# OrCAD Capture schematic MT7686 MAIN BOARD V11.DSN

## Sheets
1 22_Straping Option: size C; title: 22_Straping Option
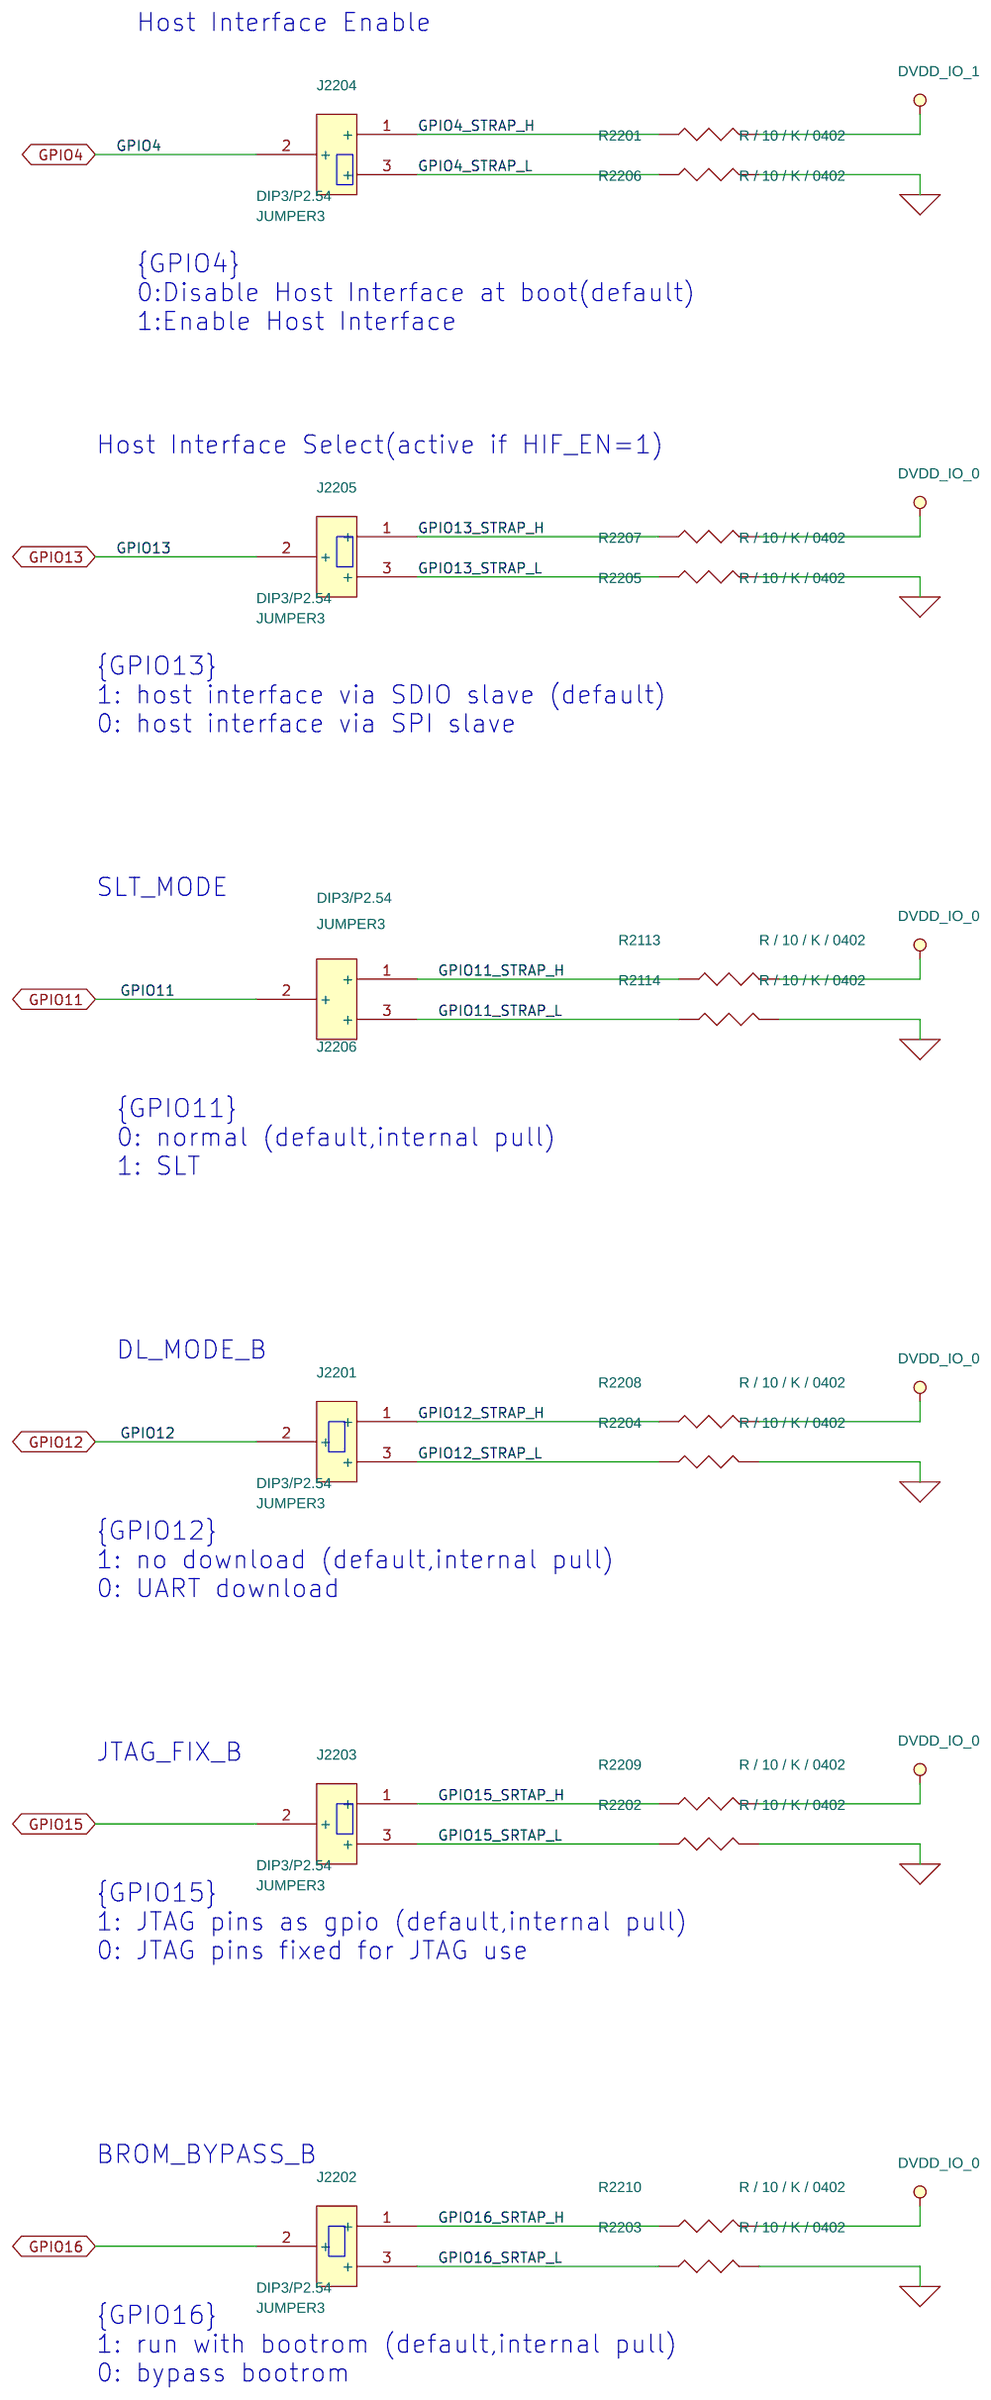
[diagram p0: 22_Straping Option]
2 90_Debug: size C; title: 90_Debug Interface
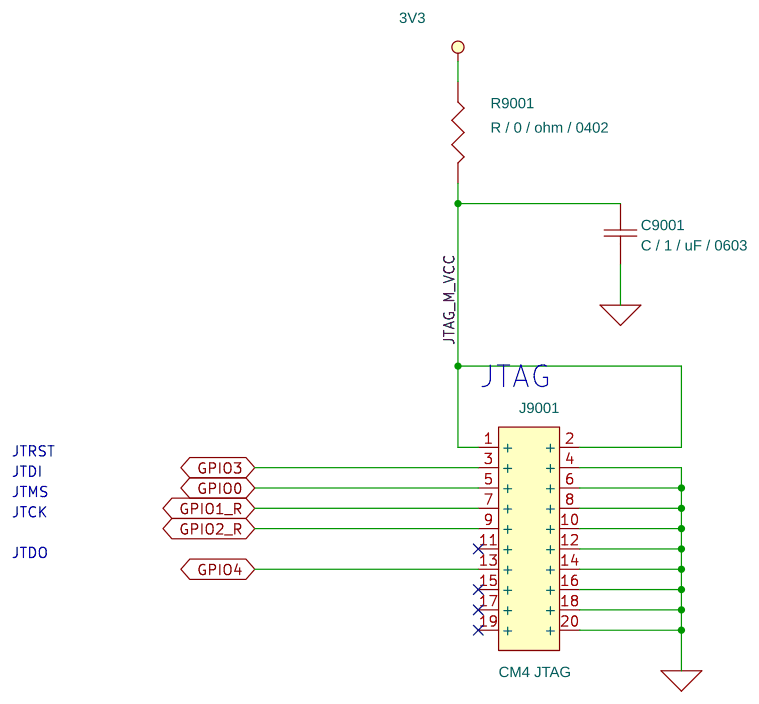
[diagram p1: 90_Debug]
3 40_external Flash: size C; title: 40_MEMORY_ Serial Flash
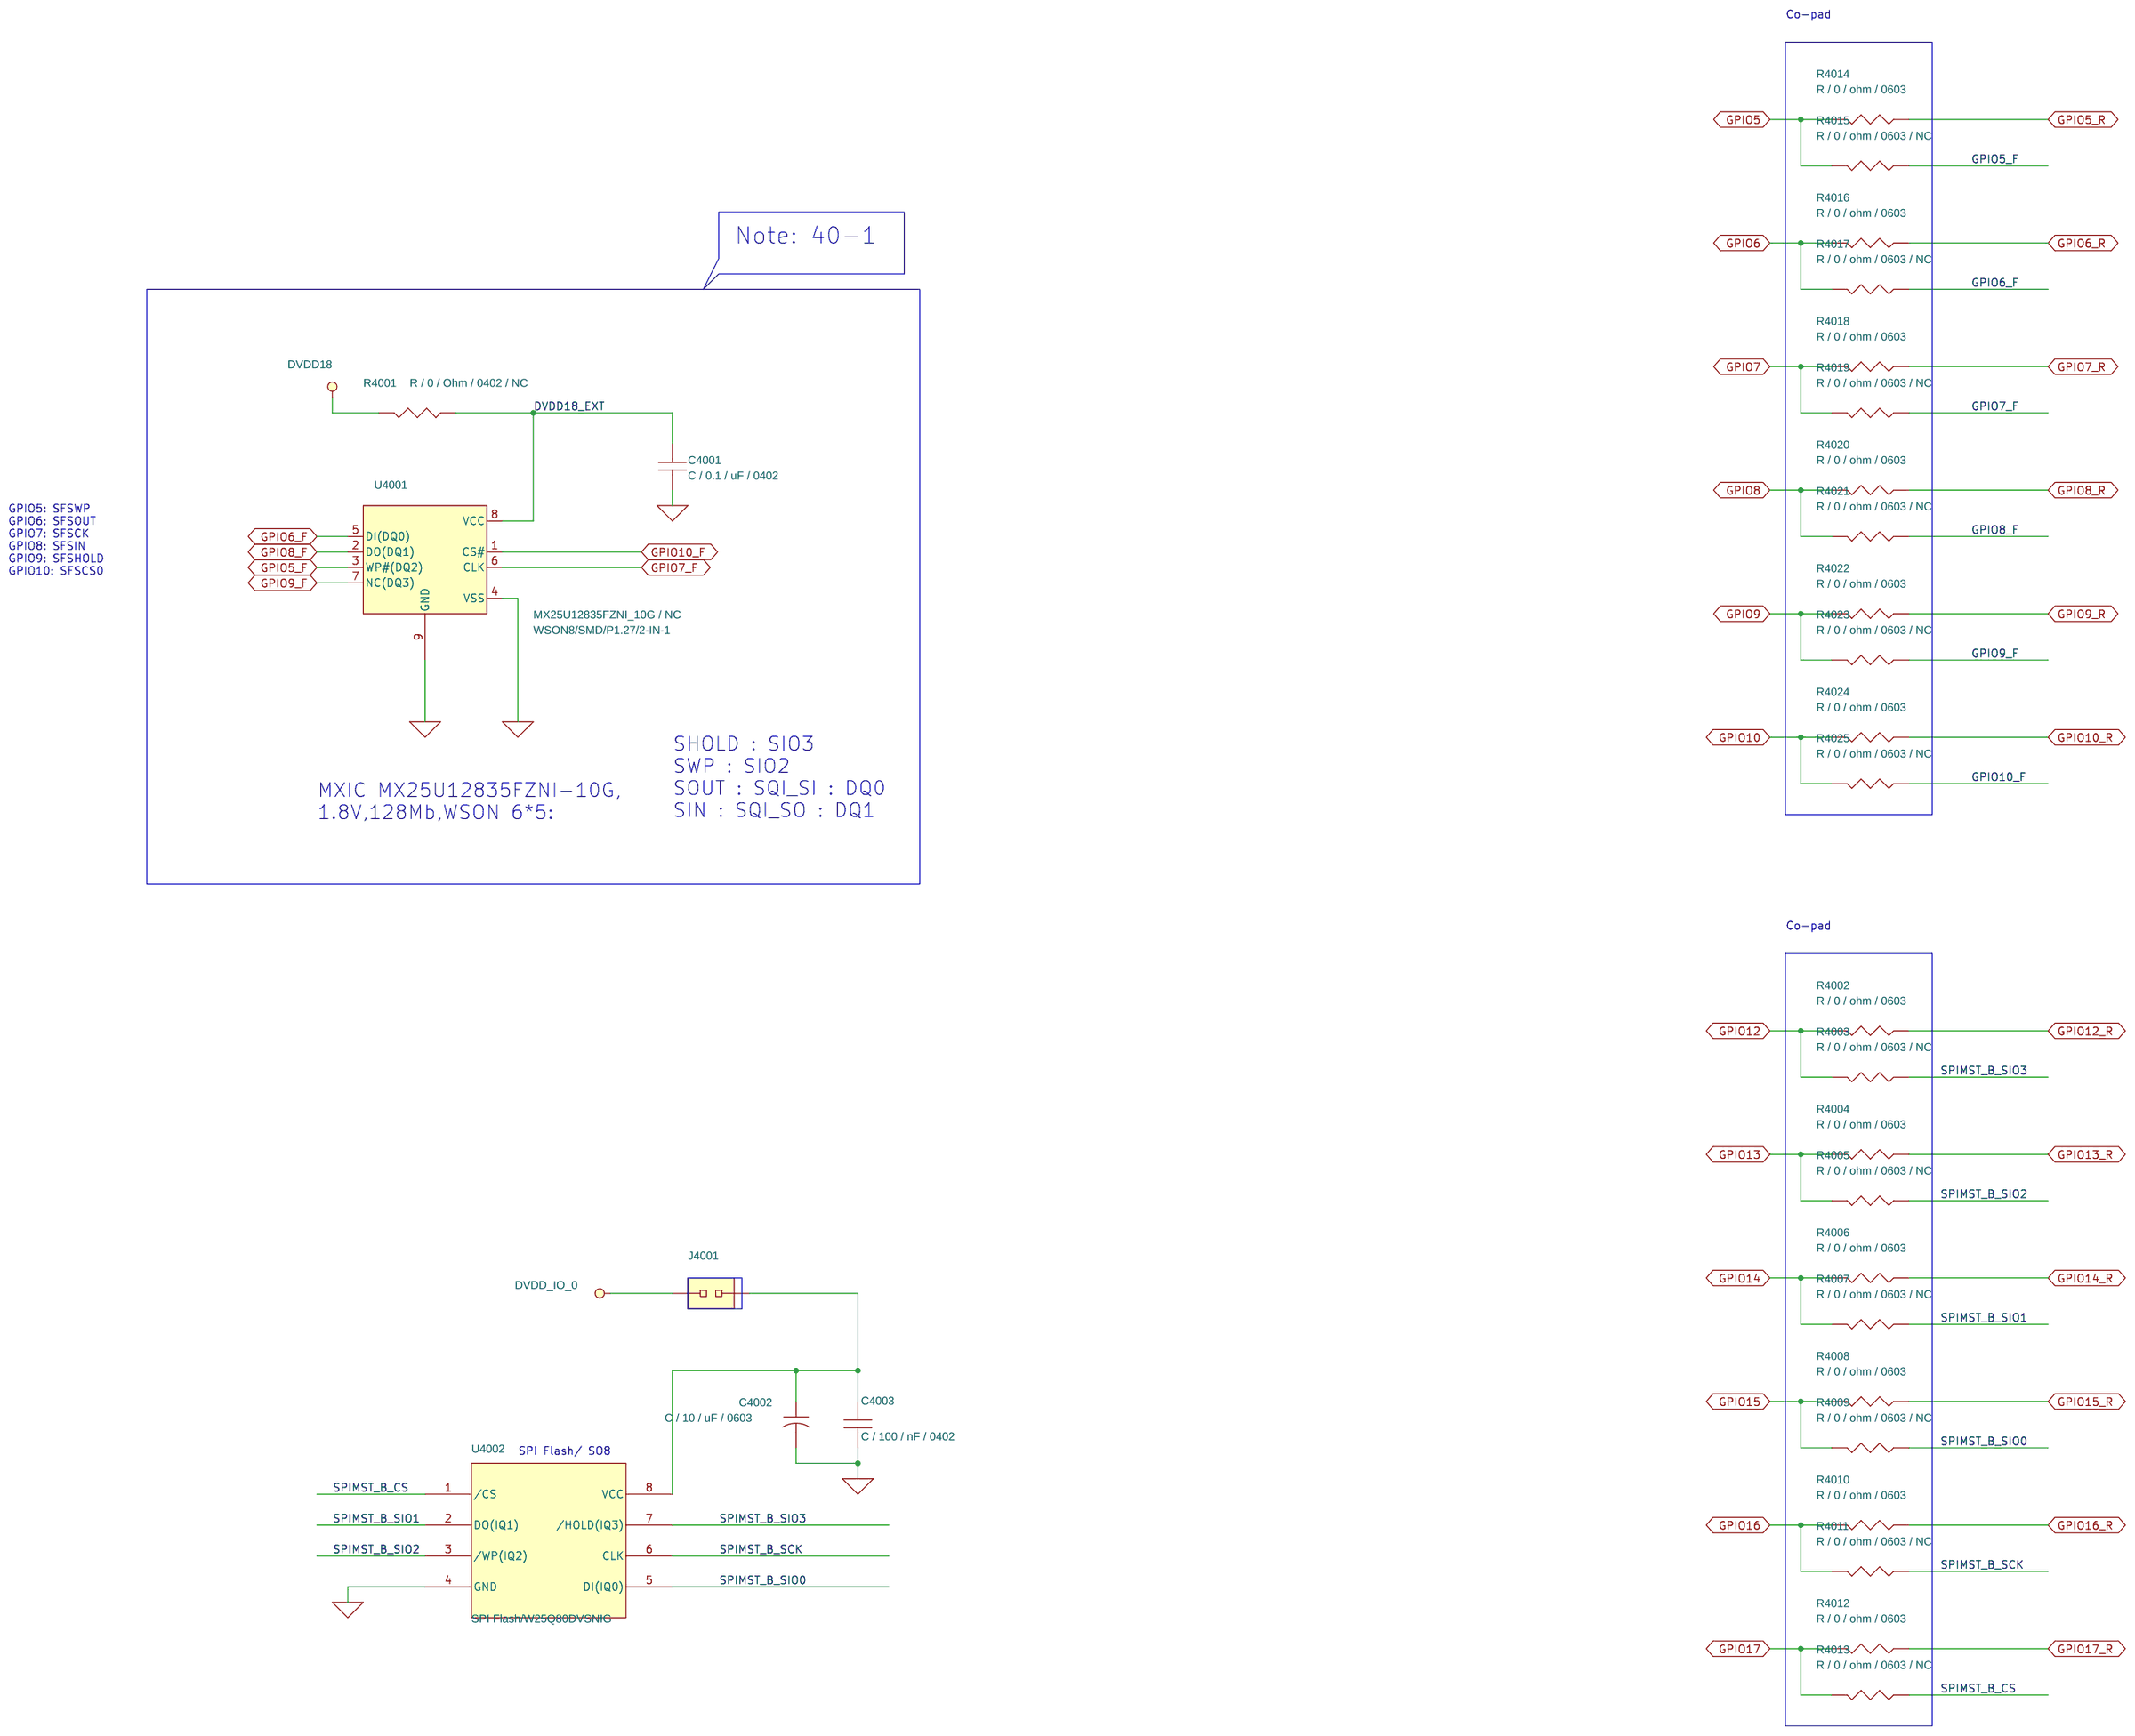
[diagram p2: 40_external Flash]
4 41_LED: size C; title: MT76x7 Main Board; rev: 3.0; company: MediaTek Inc.; note: 4_LED
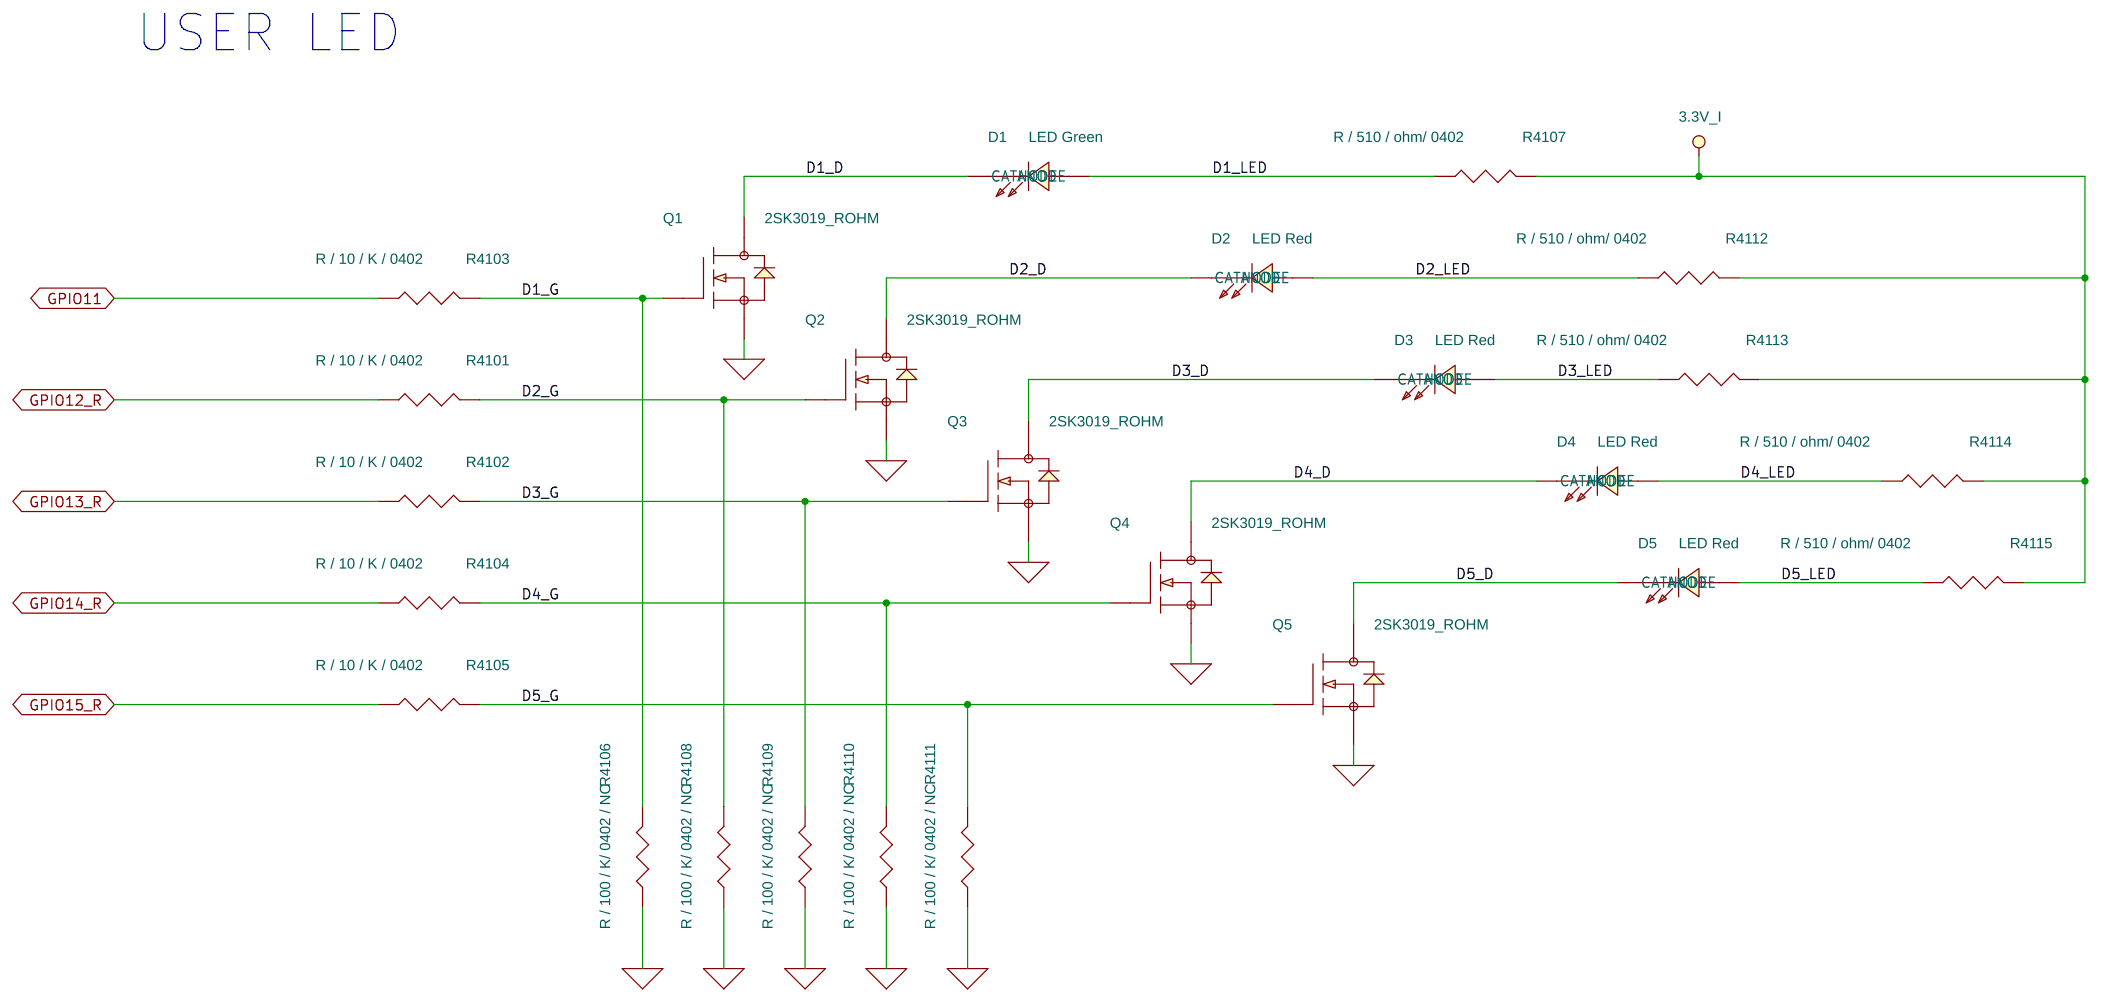
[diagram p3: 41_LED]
5 30_USB: size C; title: MT76x7 Main Board; rev: 3.0; company: MediaTek Inc.; note: 3_USB
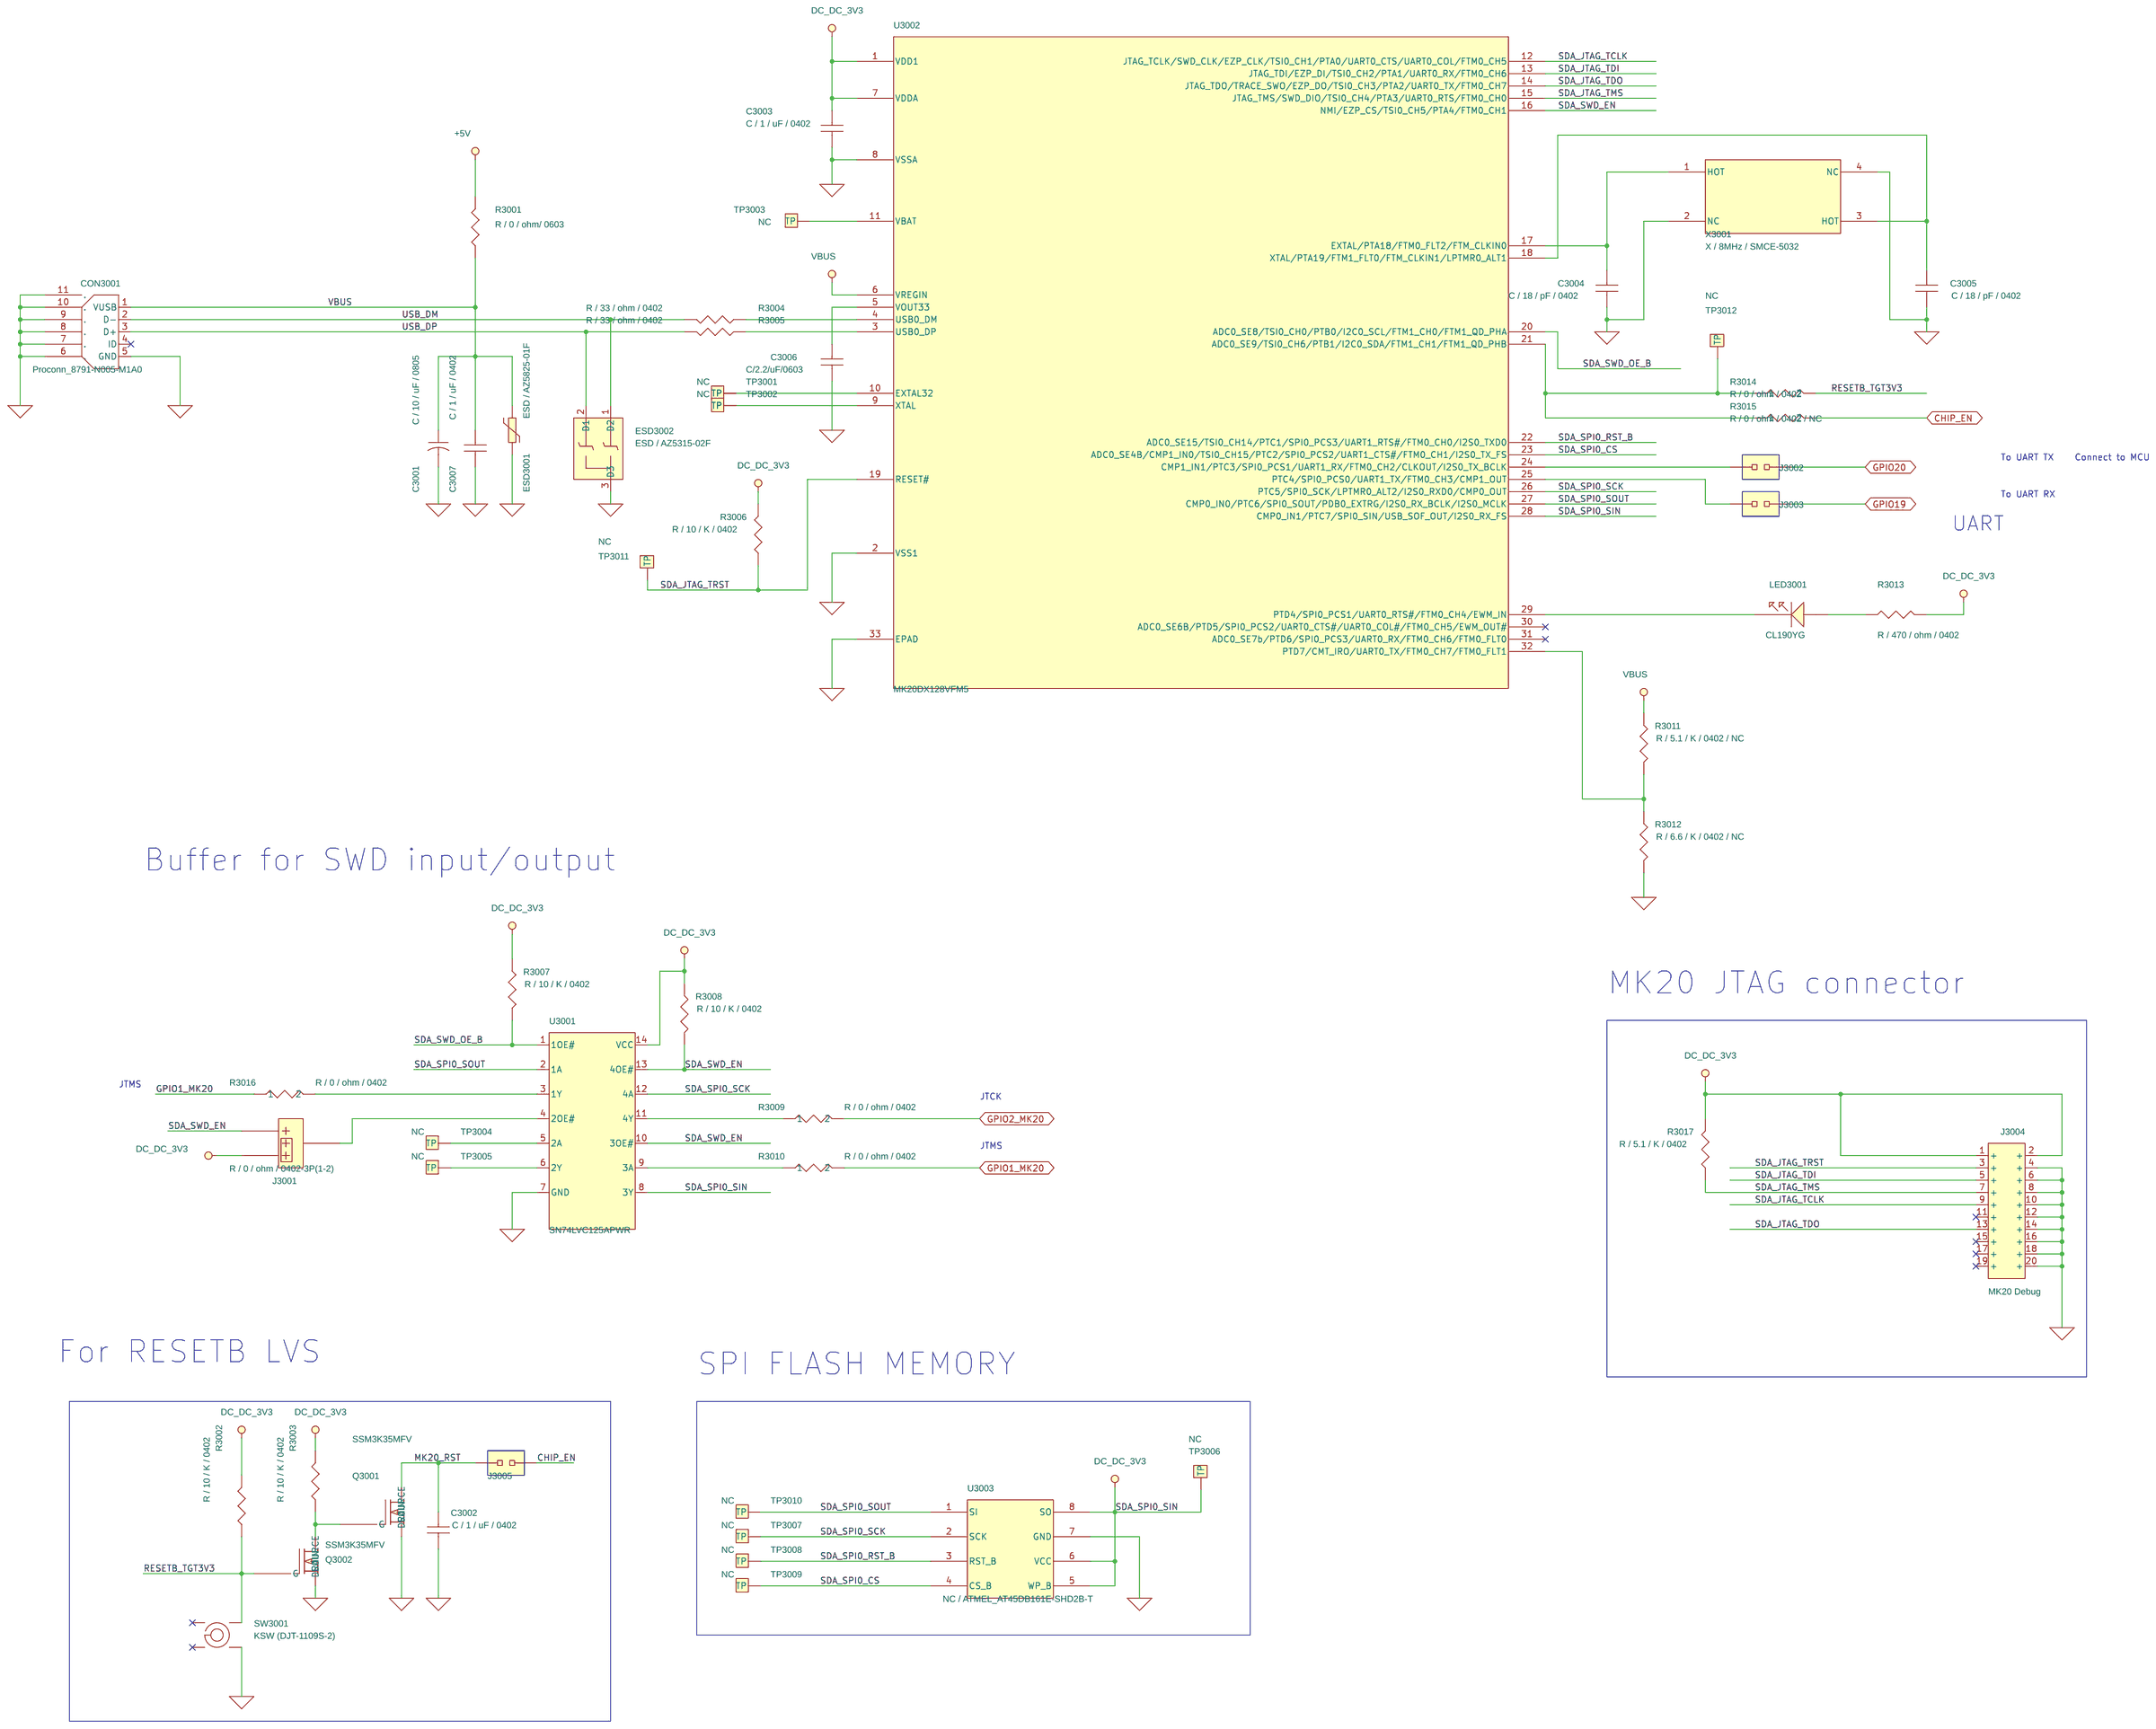
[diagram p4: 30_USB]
6 20_Power Tree: size C; title: 20_Power Tree
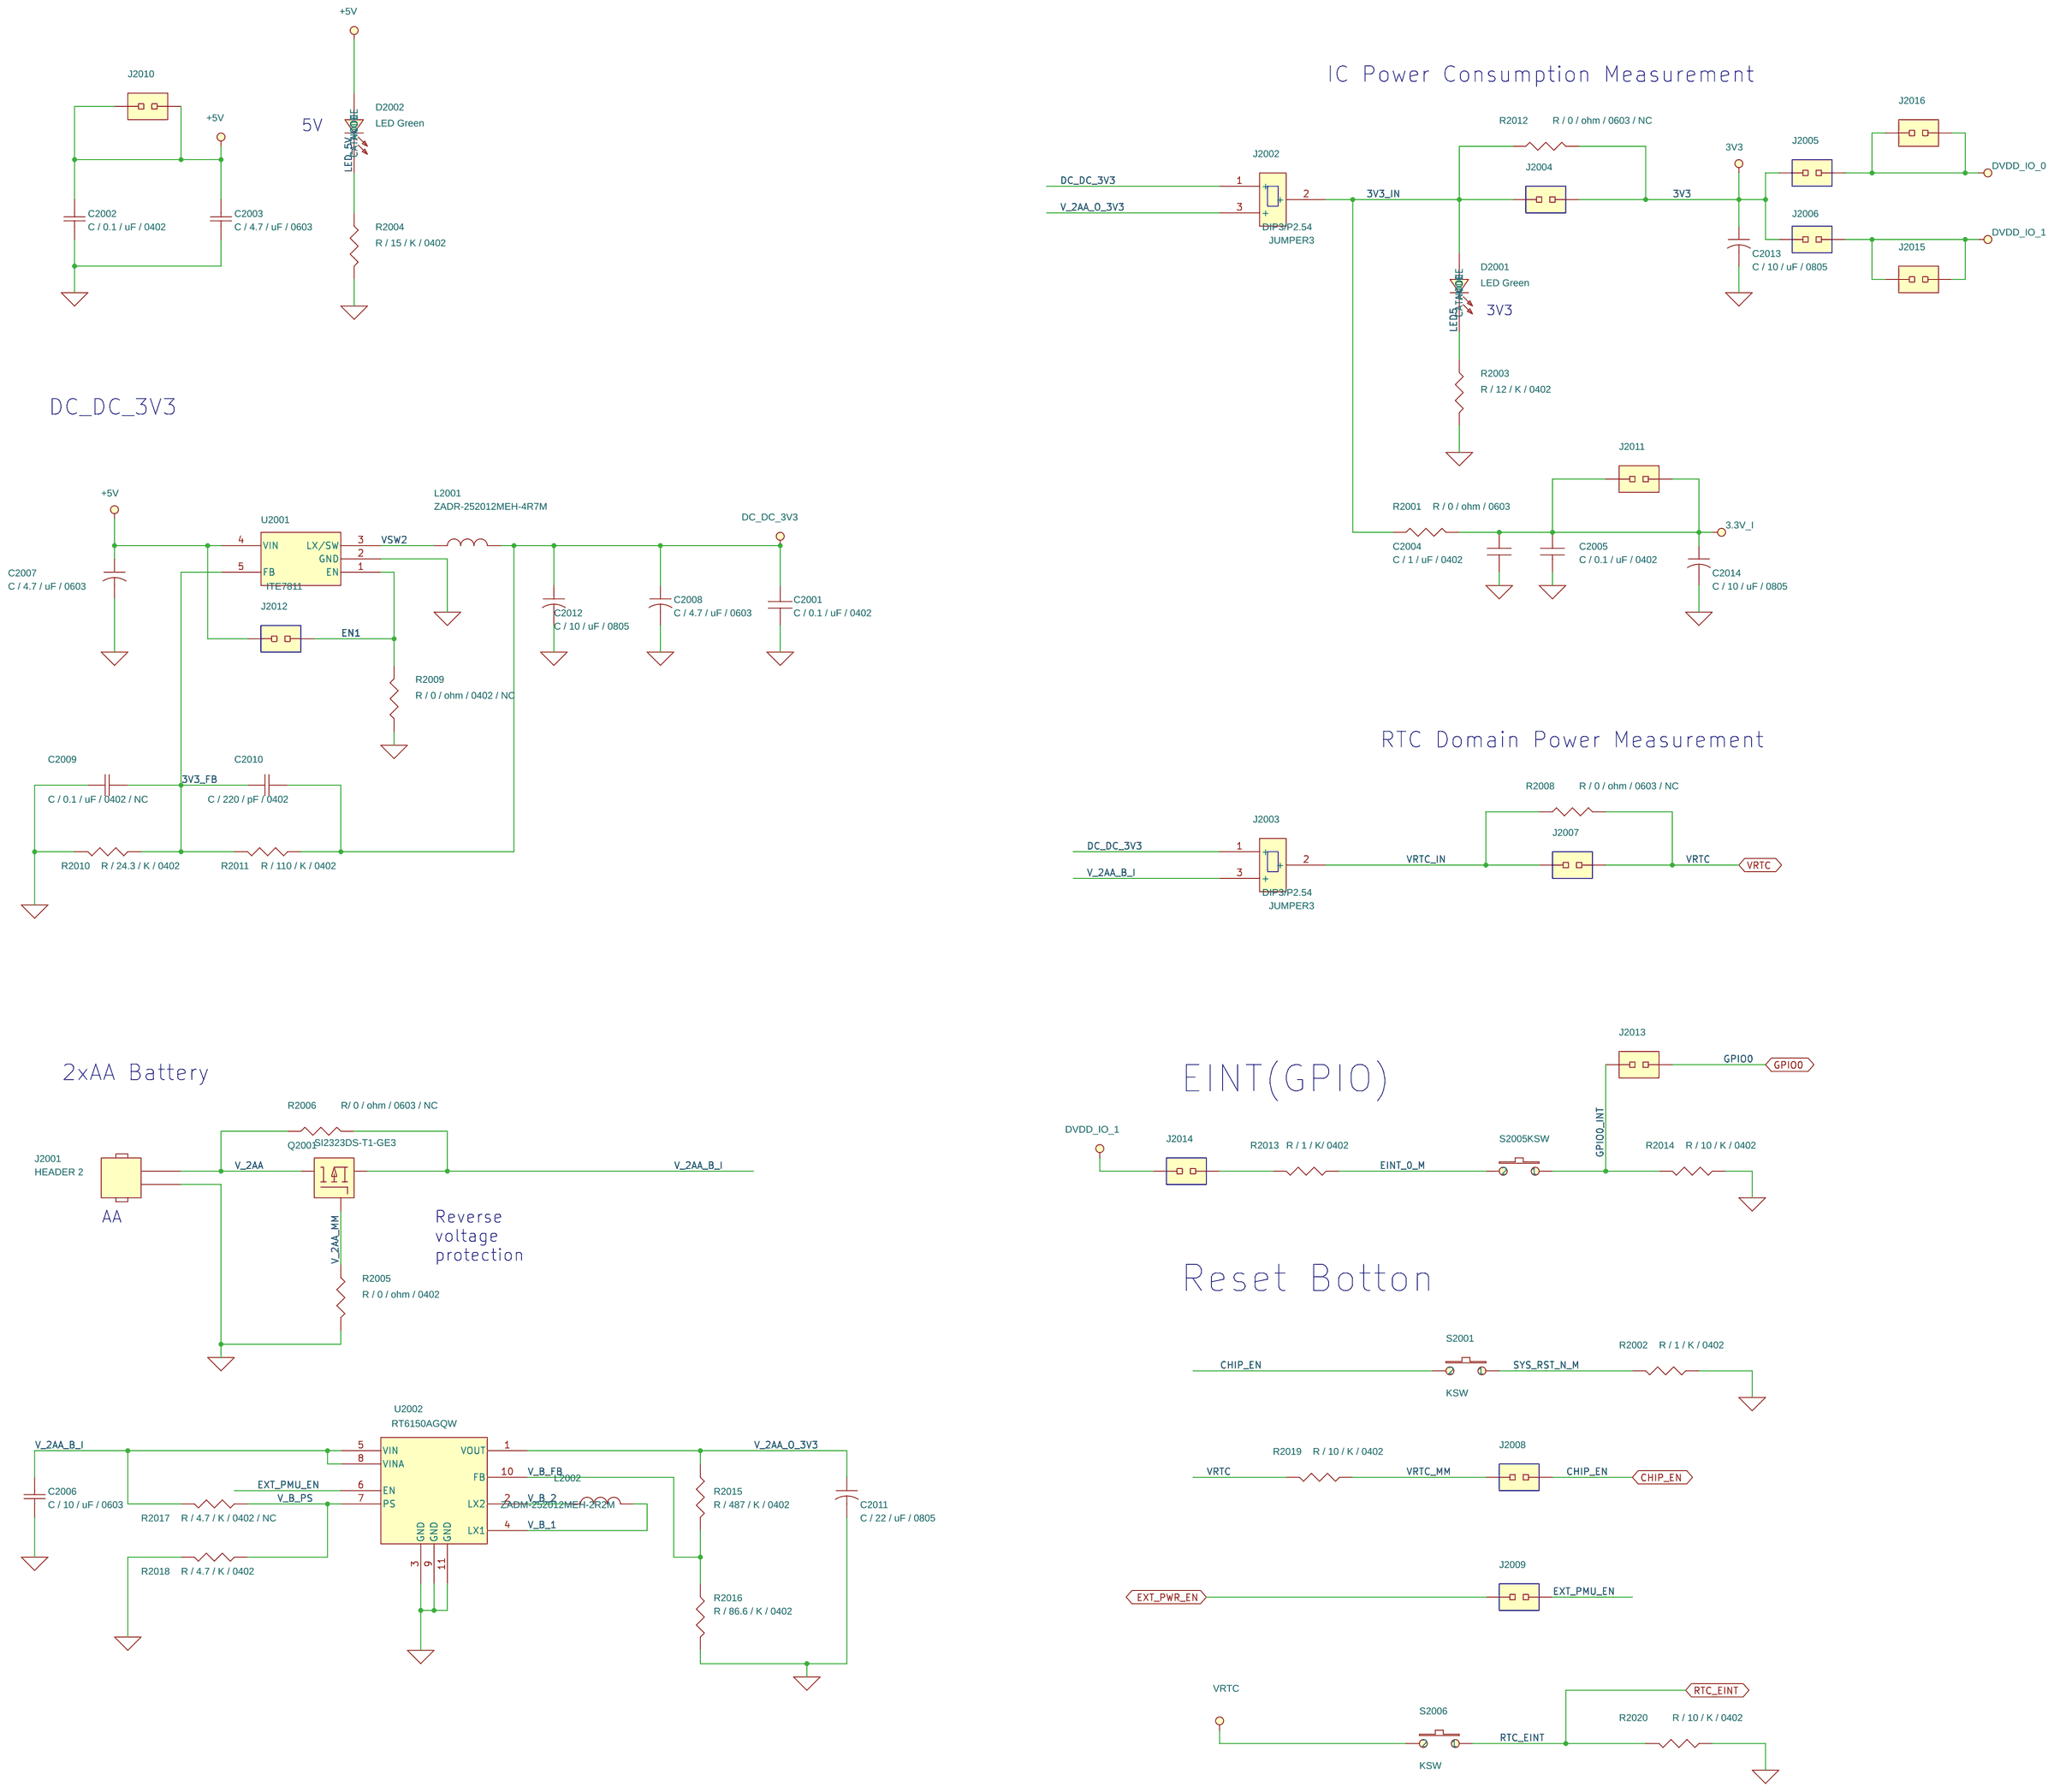
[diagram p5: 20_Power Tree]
7 21_Test Interface: size C; title: MT76x7 Main Board; rev: 3.0; company: MediaTek Inc.; note: 2_Test Interface
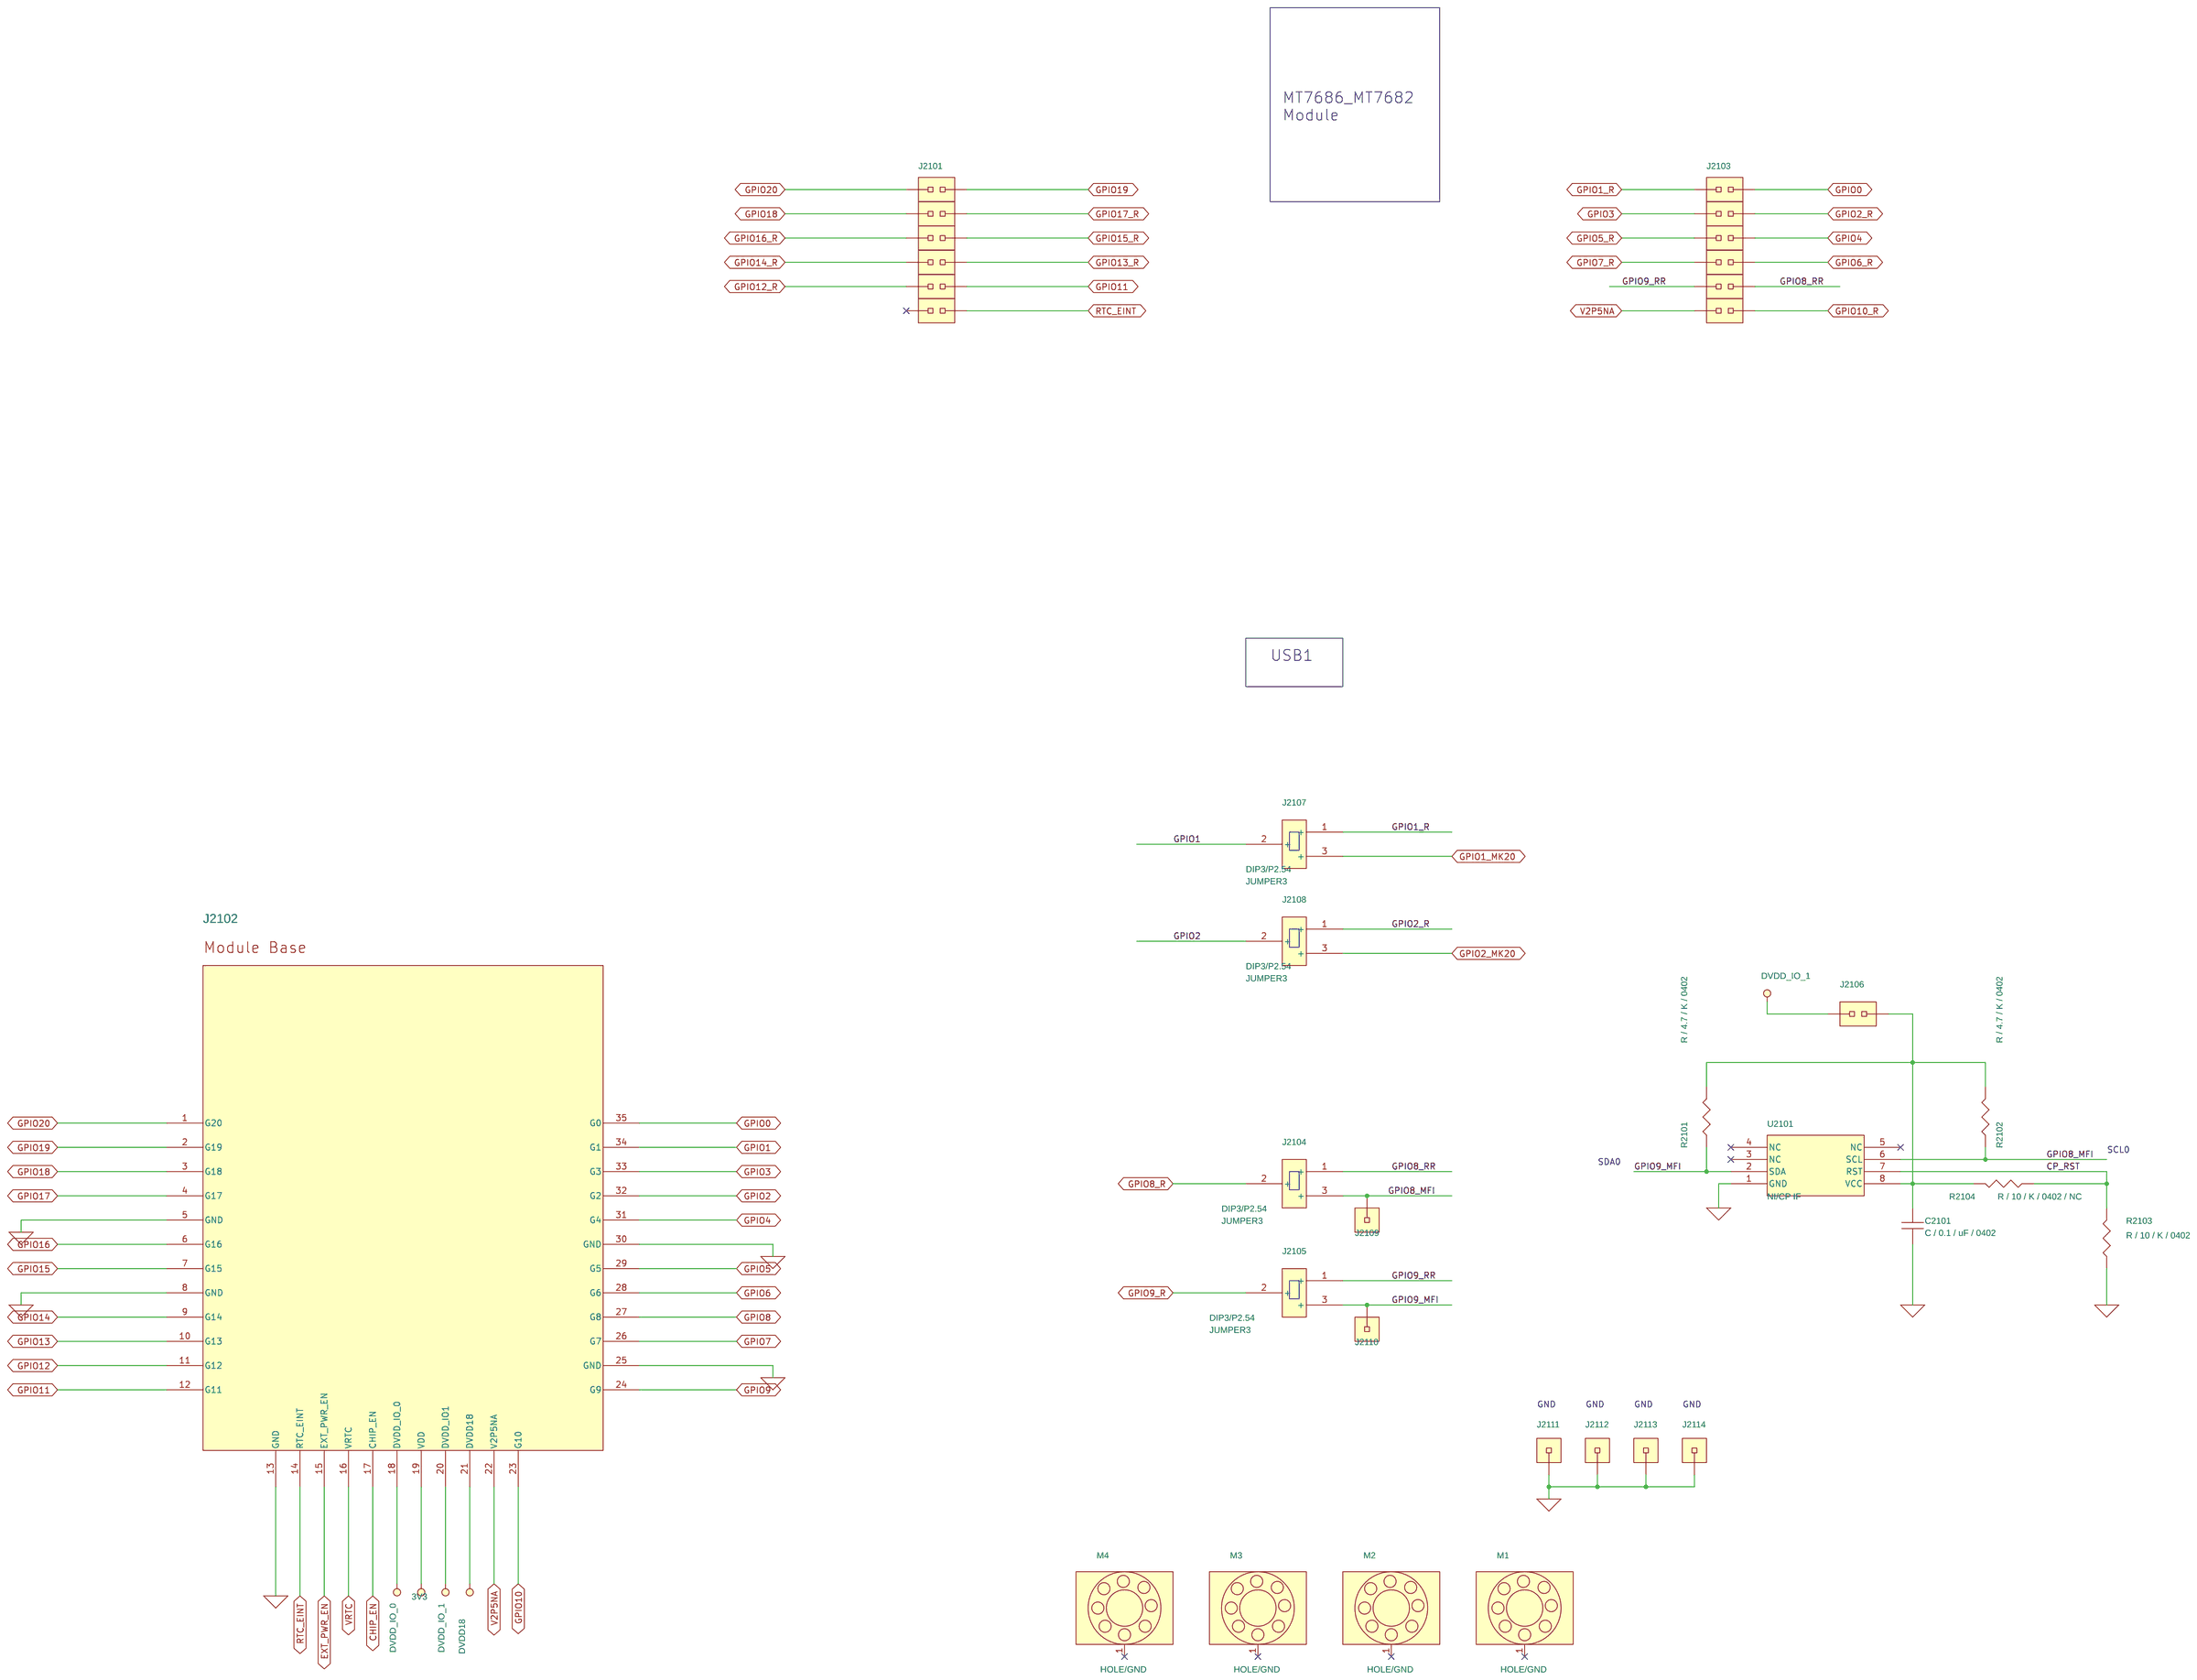
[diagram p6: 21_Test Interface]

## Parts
sheet 20_Power Tree
C2001  C / 0.1 / uF / 0402  [C0402]
C2002  C / 0.1 / uF / 0402  [C0402]
C2003  C / 4.7 / uF / 0603  [C0603]
C2004  C / 1 / uF / 0402  [C0402]
C2005  C / 0.1 / uF / 0402  [C0402]
C2006  C / 10 / uF / 0603  [C0603]
C2007  C / 4.7 / uF / 0603  [C0603]
C2008  C / 4.7 / uF / 0603  [C0603]
C2009  C / 0.1 / uF / 0402 / NC  [C0402]
C2010  C / 220 / pF / 0402  [C0402]
C2011  C / 22 / uF / 0805  [C0805]
C2012  C / 10 / uF / 0805  [C0805]
C2013  C / 10 / uF / 0805  [C0805]
C2014  C / 10 / uF / 0805  [C0805]
D2001  LED Green  [LED/SMD/0603]
D2002  LED Green  [LED/SMD/0603]
J2001  HEADER 2  [DIP2/P2.54]
J2002  JUMPER3  [DIP3/P2.54]
J2003  JUMPER3  [DIP3/P2.54]
J2004  HE2  [DIP2/P2.54]
J2005  HE2  [DIP2/P2.54]
J2006  HE2  [DIP2/P2.54]
J2007  HE2  [DIP2/P2.54]
J2008  HE2  [DIP2/P2.54]
J2009  HE2  [DIP2/P2.54]
J2010  HE2  [DIP2/P2.54]
J2011  HE2  [DIP2/P2.54]
J2012  HE2  [DIP2/P2.54]
J2013  HE2  [DIP2/P2.54]
J2014  HE2  [DIP2/P2.54]
J2015  HE2  [DIP2/P2.54]
J2016  HE2  [DIP2/P2.54]
L2001  ZADR-252012MEH-4R7M  [L/IND/SMD/VLS252010T]
L2002  ZADM-252012MEH-2R2M  [L/IND/SMD/VLS252012E]
Q2001  SI2323DS-T1-GE3  [SOT23/3P/SMD/SI2323DS]
R2001  R / 0 / ohm / 0603  [R0603]
R2002  R / 1 / K / 0402  [R0402]
R2003  R / 12 / K / 0402  [R0402]
R2004  R / 15 / K / 0402  [R0402]
R2005  R / 0 / ohm / 0402  [R0402]
R2006  R/ 0 / ohm / 0603 / NC  [R0603]
R2008  R / 0 / ohm / 0603 / NC  [R0603]
R2009  R / 0 / ohm / 0402 / NC  [R0402]
R2010  R / 24.3 / K / 0402  [R0402]
R2011  R / 110 / K / 0402  [R0402]
R2012  R / 0 / ohm / 0603 / NC  [R0603]
R2013  R / 1 / K/ 0402  [R0402]
R2014  R / 10 / K / 0402  [R0402]
R2015  R / 487 / K / 0402  [R0402]
R2016  R / 86.6 / K / 0402  [R0402]
R2017  R / 4.7 / K / 0402 / NC  [R0402]
R2018  R / 4.7 / K / 0402  [R0402]
R2019  R / 10 / K / 0402  [R0402]
R2020  R / 10 / K / 0402  [R0402]
S2001  KSW  [SW4P/DIP/WCP]
S2005  KSW  [SW4P/DIP/WCP]
S2006  KSW  [SW4P/DIP/WCP]
U2001  ITE7811  [TSOT-25/SMD/IT7811TS]
U2002  RT6150AGQW  [WDFN10/SMD/P0.5/RT6150]
sheet 21_Test Interface
C2101  C / 0.1 / uF / 0402  [C0402]
J2101  JUMPER 6x2 DIP/P2.54  [DIP6X2/P2.54]
J2102  pin to pin module  [MODULE/35P/SMD/SB-MT7686-MT7682]
J2103  JUMPER 6x2 DIP/P2.54  [DIP6X2/P2.54]
J2104  JUMPER3  [DIP3/P2.54]
J2105  JUMPER3  [DIP3/P2.54]
J2106  HE2  [DIP2/P2.54]
J2107  JUMPER3  [DIP3/P2.54]
J2108  JUMPER3  [DIP3/P2.54]
J2109  JUMPER 1x1 DIP/P2.54  [DIP1/P2.54]
J2110  JUMPER 1x1 DIP/P2.54  [DIP1/P2.54]
J2111  JUMPER 1x1 DIP/P2.54  [DIP1/P2.54]
J2112  JUMPER 1x1 DIP/P2.54  [DIP1/P2.54]
J2113  JUMPER 1x1 DIP/P2.54  [DIP1/P2.54]
J2114  JUMPER 1x1 DIP/P2.54  [DIP1/P2.54]
M1  HOLE/GND  [HOLE/NPTH/D3]
M2  HOLE/GND  [HOLE/NPTH/D3]
M3  HOLE/GND  [HOLE/NPTH/D3]
M4  HOLE/GND  [HOLE/NPTH/D3]
R2101  R / 4.7 / K / 0402  [R0402/FCS]
R2102  R / 4.7 / K / 0402  [R0402/FCS]
R2103  R / 10 / K / 0402  [R0402]
R2104  R / 10 / K / 0402 / NC  [R0402]
U2101  NI/CP IF  [USON8/SMD/P0.5/CP]
sheet 22_Straping Option
J2201  JUMPER3  [DIP3/P2.54]
J2202  JUMPER3  [DIP3/P2.54]
J2203  JUMPER3  [DIP3/P2.54]
J2204  JUMPER3  [DIP3/P2.54]
J2205  JUMPER3  [DIP3/P2.54]
J2206  JUMPER3  [DIP3/P2.54]
R2113  R / 10 / K / 0402  [R0402]
R2114  R / 10 / K / 0402  [R0402]
R2201  R / 10 / K / 0402  [R0402]
R2202  R / 10 / K / 0402  [R0402]
R2203  R / 10 / K / 0402  [R0402]
R2204  R / 10 / K / 0402  [R0402]
R2205  R / 10 / K / 0402  [R0402]
R2206  R / 10 / K / 0402  [R0402]
R2207  R / 10 / K / 0402  [R0402]
R2208  R / 10 / K / 0402  [R0402]
R2209  R / 10 / K / 0402  [R0402]
R2210  R / 10 / K / 0402  [R0402]
sheet 30_USB
C3001  C / 10 / uF / 0805  [C0805]
C3002  C / 1 / uF / 0402  [C0402]
C3003  C / 1 / uF / 0402  [C0402]
C3004  C / 18 / pF / 0402  [C0402]
C3005  C / 18 / pF / 0402  [C0402]
C3006  C/2.2/uF/0603  [C0603]
C3007  C / 1 / uF / 0402  [C0402]
CON3001  Proconn_8791-N005-M1A0  [MICROUSB/5P/SMD/P0.65/R/8791-N005-M1A0]
ESD3001  ESD / AZ5825-01F  [VR0402]
ESD3002  ESD / AZ5315-02F  [ESD/SMD/AZ5315-02F]
J3001  R / 0 / ohm / 0402-3P(1-2)  [R0402/(1-2)]
J3002  HE2  [DIP2/P2.54]
J3003  HE2  [DIP2/P2.54]
J3004  MK20 Debug  [DIP10X2/W/H/IDE/P2.54]
J3005  HE2  [DIP2/P2.54]
LED3001  CL190YG  [LED190]
Q3001  SSM3K35MFV  [2-1L1B/SMD/SSM3K35MFV]
Q3002  SSM3K35MFV  [2-1L1B/SMD/SSM3K35MFV]
R3001  R / 0 / ohm/ 0603  [R0603]
R3002  R / 10 / K / 0402  [R0402]
R3003  R / 10 / K / 0402  [R0402]
R3004  R / 33 / ohm / 0402  [R0402]
R3005  R / 33 / ohm / 0402  [R0402]
R3006  R / 10 / K / 0402  [R0402]
R3007  R / 10 / K / 0402  [R0402]
R3008  R / 10 / K / 0402  [R0402]
R3009  R / 0 / ohm / 0402  [R0402]
R3010  R / 0 / ohm / 0402  [R0402]
R3011  R / 5.1 / K / 0402 / NC  [R0402]
R3012  R / 6.6 / K / 0402 / NC  [R0402]
R3013  R / 470 / ohm / 0402  [R0402]
R3014  R / 0 / ohm / 0402  [R0402]
R3015  R / 0 / ohm / 0402 / NC  [R0402]
R3016  R / 0 / ohm / 0402  [R0402]
R3017  R / 5.1 / K / 0402  [R0402]
SW3001  KSW (DJT-1109S-2)  [SW/4P/SMD/SHOWMAN]
TP3001  NC  [TP30MIL]
TP3002  NC  [TP30MIL]
TP3003  NC  [TP30MIL]
TP3004  NC  [TP40MIL]
TP3005  NC  [TP40MIL]
TP3006  NC  [TP30MIL]
TP3007  NC  [TP30MIL]
TP3008  NC  [TP30MIL]
TP3009  NC  [TP30MIL]
TP3010  NC  [TP30MIL]
TP3011  NC  [TP30MIL]
TP3012  NC  [TP40MIL]
U3001  SN74LVC125APWR  [TSSOP14/SMD/P0.65/DRV603]
U3002  MK20DX128VFM5  [QFN32/SMD/P0.5/98ARE10566D]
U3003  NC / ATMEL_AT45DB161E-SHD2B-T  [SOIC8/SMD]
X3001  X / 8MHz / SMCE-5032  [CRYS/SMD/D5.0X3.2/5XAA08000152KF80Q3]
sheet 40_external Flash
C4001  C / 0.1 / uF / 0402  [C0402]
C4002  C / 10 / uF / 0603  [C0603]
C4003  C / 100 / nF / 0402  [C0402]
J4001  HE2  [DIP2/P2.54]
R4001  R / 0 / Ohm / 0402 / NC  [R0402]
R4002  R / 0 / ohm / 0603  [R0603]
R4003  R / 0 / ohm / 0603 / NC  [R0603]
R4004  R / 0 / ohm / 0603  [R0603]
R4005  R / 0 / ohm / 0603 / NC  [R0603]
R4006  R / 0 / ohm / 0603  [R0603]
R4007  R / 0 / ohm / 0603 / NC  [R0603]
R4008  R / 0 / ohm / 0603  [R0603]
R4009  R / 0 / ohm / 0603 / NC  [R0603]
R4010  R / 0 / ohm / 0603  [R0603]
R4011  R / 0 / ohm / 0603 / NC  [R0603]
R4012  R / 0 / ohm / 0603  [R0603]
R4013  R / 0 / ohm / 0603 / NC  [R0603]
R4014  R / 0 / ohm / 0603  [R0603]
R4015  R / 0 / ohm / 0603 / NC  [R0603]
R4016  R / 0 / ohm / 0603  [R0603]
R4017  R / 0 / ohm / 0603 / NC  [R0603]
R4018  R / 0 / ohm / 0603  [R0603]
R4019  R / 0 / ohm / 0603 / NC  [R0603]
R4020  R / 0 / ohm / 0603  [R0603]
R4021  R / 0 / ohm / 0603 / NC  [R0603]
R4022  R / 0 / ohm / 0603  [R0603]
R4023  R / 0 / ohm / 0603 / NC  [R0603]
R4024  R / 0 / ohm / 0603  [R0603]
R4025  R / 0 / ohm / 0603 / NC  [R0603]
U4001  MX25U12835FZNI_10G / NC  [WSON8/SMD/P1.27/2-IN-1]
U4002  SPI Flash/W25Q80DVSNIG  [SOIC8/SMD/P1.27/W25Q80DV]
sheet 41_LED
D1  LED Green  [LED/SMD/0603]
D2  LED Red  [LED/SMD/0603]
D3  LED Red  [LED/SMD/0603]
D4  LED Red  [LED/SMD/0603]
D5  LED Red  [LED/SMD/0603]
Q1  2SK3019_ROHM  [SC-75]
Q2  2SK3019_ROHM  [SC-75]
Q3  2SK3019_ROHM  [SC-75]
Q4  2SK3019_ROHM  [SC-75]
Q5  2SK3019_ROHM  [SC-75]
R4101  R / 10 / K / 0402  [R0402]
R4102  R / 10 / K / 0402  [R0402]
R4103  R / 10 / K / 0402  [R0402]
R4104  R / 10 / K / 0402  [R0402]
R4105  R / 10 / K / 0402  [R0402]
R4106  R / 100 / K/ 0402 / NC  [R0402]
R4107  R / 510 / ohm/ 0402  [R0402]
R4108  R / 100 / K/ 0402 / NC  [R0402]
R4109  R / 100 / K/ 0402 / NC  [R0402]
R4110  R / 100 / K/ 0402 / NC  [R0402]
R4111  R / 100 / K/ 0402 / NC  [R0402]
R4112  R / 510 / ohm/ 0402  [R0402]
R4113  R / 510 / ohm/ 0402  [R0402]
R4114  R / 510 / ohm/ 0402  [R0402]
R4115  R / 510 / ohm/ 0402  [R0402]
sheet 90_Debug
C9001  C / 1 / uF / 0603  [C0603]
J9001  CM4 JTAG  [DIP10X2/W/H/IDE/P2.54]
R9001  R / 0 / ohm / 0402  [R0402]

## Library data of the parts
C2001 C2004 C2005 C2101 C4001 = CAPACITOR_NON-POL: PART_NUMBER: C21-0402M104Y1EWLS; PART_TYPE: C21
C2002 C2003 C2006 = CAP_0402
C2007 = CAP_0603
C2008 = CAP_0805_0603
C2009 C2010 C9001 = CAP_0402: 1st Part Field: 0402
C2011-C2014 C3001 = CAP_0805
D1-D5 D2001 D2002 = LED_0603_0402
J2001 = HEADER_2
J2002 J2003 J2104 J2105 J2107 J2108 J2201-J2206 = JUMPER3
J2004-J2016 J2106 J3002 J3003 J3005 J4001 = JMP2B
L2001 L2002 = L_2.5*2.0
Q2001 = MOSFET_I_EP_GSD: MOSFET P-CH 20V 3.7A SOT23-3; Distributor_Part_Number: SI2323DS-T1-GE3CT-ND; Mfr_Name: Vishay; TI_Part_No: TI-MOSFET-SI2323DS-T1-GE3
R2001 = R_510_ohm_0402
R2002 R2020 R4001 = RESISTOR: PART_NUMBER: R31-0201J0R00FWLS0; PART_TYPE: R31
R2003-R2006 R2008 R2012 R2015 R2016 R3001 R4101-R4115 = RES_0603_0
R2009 = RES_0402_5
R2010 = RES_0402_2
R2011 = RES_0402_3
R2013 R2014 R2019 R2103 R2104 R9001 = RES_0402_1
R2017 R2018 = R_0402
S2001 = SW_PUSHBUTTON
S2005 = SW_PUSHBUTTON_1
S2006 = SW_PUSHBUTTON_2
U2001 = REG_CAT7101
U2002 = REG_CAT7117_4
J2101 J2103 = JUMPER_10x2_DIP_P2_4.54
J2102 = S500_3
J2109-J2114 = JUMPER_1x1_DIP_P2.54
M1-M4 = HOLE_3_0.5mm
R2101 R2102 = RES_0402
U2101 = CP_IF
R2113 R2114 R2201-R2210 R4002-R4025 = R_4.7_K_0402
C3002 C3003 C3007 = C_1000_nF_0402
C3004 C3005 = C_18_pF_0402
C3006 = C_10_uF_0603_X5R
CON3001 = USB_CON_MINI_AB_0: HRS MINI USB connector; Vendor: FOXLINK
ESD3001 = ESD_AZ5825-01F
ESD3002 = ESD_AZ5315-02F
J3001 = CON3_0
J3004 J9001 = CON20AP
LED3001 = LED_1
Q3001 Q3002 = MOSFET_N_2
R3002 R3003 R3006-R3008 R3011 R3012 R3017 = R_10_K_0402
R3004 R3005 = R_0_ohm_0402
R3009 = Resistor_5: R 0 J 1/16W 0402; Vendor: CYNTEC
R3010 = Resistor_5_1: R 0 J 1/16W 0402; Vendor: CYNTEC
R3013 = RESISTOR
R3014 = Resistor_5_3: R 0 J 1/16W 0402; Vendor: CYNTEC
R3015 = Resistor_5_4: R 0 J 1/16W 0402; Vendor: CYNTEC
R3016 = Resistor_5_2: R 0 J 1/16W 0402; Vendor: CYNTEC
SW3001 = SW_MEMBRANE_0
TP3001-TP3012 = T_POINT_F_2
U3001 = CON_10_AXT510124_0: ebom: USB
U3002 = 74ALVC164245_2: Vendor: TI
U3003 = X_26_MHz_TZ2300A_0
X3001 = TCVCXO_1: TCVCXO 26MHz; Customer PN: 70TZ1879A00F; Manufacturer Part Number: TZ1879A; Part Type: Crystal\OSC; Vendor: Taisaw
C4002 = C0805
C4003 = C0603
U4001 = EN25Q64_0
U4002 = SPIFlash-Winbond25P16_2
Q1-Q5 = MPF6659_0: Layer: Top

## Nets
3.3V_I: C2004.1 C2005.1 C2014.1 J2011.1 J2011.2 R2001.2 R4107.1 R4112.1 R4113.1 R4114.1 R4115.1
3V3: C2013.1 J2004.2 J2005.1 J2006.1 J2102.19(VDD) R2012.2 R9001.2
3V3_FB: C2009.2 C2010.1 R2010.1 R2011.2 U2001.5(FB)
3V3_IN: D2001.1(ANODE) J2002.2(+) J2004.1 R2001.1 R2012.1
+5V: C2002.1 C2003.1 C2007.1 D2002.1(ANODE) J2010.1 J2010.2 J2012.1 R3001.2 U2001.4(VIN)
DVDD18: J2102.21(DVDD18) R4001.2
DVDD18_EXT: C4001.1 R4001.1 U4001.8(VCC)
DVDD_IO_0: J2005.2 J2016.1 J2016.2 J2102.18(DVDD_IO_0) J4001.1 R2113.2 R2207.2 R2208.2 R2209.2 R2210.2
DVDD_IO_1: J2006.2 J2014.1 J2015.1 J2015.2 J2102.20(DVDD_IO1) J2106.1 R2201.2
GND: C2001.2 C2002.2 C2003.2 C2004.2 C2005.2 C2006.2 C2007.2 C2008.2 C2009.1 C2011.2 C2012.2 C2013.2 C2014.2 C2101.2 C3001.2 C3002.2 C3003.2 C3004.2 C3005.2 C3006.2 C3007.2 C4001.2 C4002.2 C4003.2 C9001.2 CON3001.5(GND) CON3001.6(.) CON3001.7(.) CON3001.8(.) CON3001.9(.) CON3001.10(.) CON3001.11(.) ESD3001.2 ESD3002.3(D3) J2001.2 J2102.5(GND) J2102.8(GND) J2102.13(GND) J2102.25(GND) J2102.30(GND) J2111.1 J2112.1 J2113.1 J2114.1 J3004.4(+) J3004.6(+) J3004.8(+) J3004.10(+) J3004.12(+) J3004.14(+) J3004.16(+) J3004.18(+) J3004.20(+) J9001.4(+) J9001.6(+) J9001.8(+) J9001.10(+) J9001.12(+) J9001.14(+) J9001.16(+) J9001.18(+) J9001.20(+) Q1.1(S) Q2.1(S) Q3.1(S) Q4.1(S) Q5.1(S) Q3001.2(SOURCE) Q3002.2(SOURCE) R2002.1 R2003.2 R2004.2 R2005.2 R2009.1 R2010.2 R2014.2 R2016.2 R2018.1 R2020.1 R2103.2 R2114.2 R2202.2 R2203.2 R2204.2 R2205.2 R2206.2 R3012.2 R4106.2 R4108.2 R4109.2 R4110.2 R4111.2 SW3001.3 U2001.2(GND) U2002.3(GND) U2002.9(GND) U2002.11(GND) U2101.1(GND) U3001.7(GND) U3002.2(VSS1) U3002.8(VSSA) U3002.33(EPAD) U3003.7(GND) U4001.4(VSS) U4001.9(GND) U4002.4(GND) X3001.2(NC) X3001.4(NC)
V2P5NA: J2102.22(V2P5NA) J2103.11
VBUS: C3001.1 C3007.1 CON3001.1(VUSB) ESD3001.1 R3001.1 R3011.1 U3002.6(VREGIN)
CHIP_EN: J2008.2 J2102.17(CHIP_EN) J3005.2 R3015.2 S2001.2
CP_RST: R2103.1 R2104.2 U2101.7(RST)
D1_D: D1.2(CATHODE) Q1.3(D)
D1_G: Q1.2(G) R4103.1 R4106.1
D1_LED: D1.1(ANODE) R4107.2
D2_D: D2.2(CATHODE) Q2.3(D)
D2_G: Q2.2(G) R4101.1 R4108.1
D2_LED: D2.1(ANODE) R4112.2
D3_D: D3.2(CATHODE) Q3.3(D)
D3_G: Q3.2(G) R4102.1 R4109.1
D3_LED: D3.1(ANODE) R4113.2
D4_D: D4.2(CATHODE) Q4.3(D)
D4_G: Q4.2(G) R4104.1 R4110.1
D4_LED: D4.1(ANODE) R4114.2
D5_D: D5.2(CATHODE) Q5.3(D)
D5_G: Q5.2(G) R4105.1 R4111.1
D5_LED: D5.1(ANODE) R4115.2
DC_DC_3V3: C2001.1 C2008.1 C2010.2 C2012.1 C3003.1 J2002.1(+) J2003.1(+) J3001.1 J3004.1(+) J3004.2(+) L2001.2 R2011.1 R3002.1 R3003.1 R3006.1 R3007.1 R3008.1 R3013.2 R3017.1 U3001.14(VCC) U3002.1(VDD1) U3002.7(VDDA) U3003.5(WP_B) U3003.6(VCC)
EINT_0_M: R2013.2 S2005.2
EN1: J2012.2 R2009.2 U2001.1(EN)
EXT_PMU_EN: J2009.2 U2002.6(EN)
EXT_PWR_EN: J2009.1 J2102.15(EXT_PWR_EN)
GPIO0: J2013.2 J2102.35(G0) J2103.2 J9001.5(+)
GPIO0_INT: J2013.1 R2014.1 S2005.1
GPIO1: J2102.34(G1) J2107.2(+)
GPIO1_MK20: J2107.3(+) R3010.2 R3016.1
GPIO1_R: J2103.1 J2107.1(+) J9001.7(+)
GPIO2: J2102.32(G2) J2108.2(+)
GPIO2_MK20: J2108.3(+) R3009.2
GPIO2_R: J2103.4 J2108.1(+) J9001.9(+)
GPIO3: J2102.33(G3) J2103.3 J9001.3(+)
GPIO4: J2102.31(G4) J2103.6 J2204.2(+) J9001.13(+)
GPIO4_STRAP_H: J2204.1(+) R2201.1
GPIO4_STRAP_L: J2204.3(+) R2206.1
GPIO5: J2102.29(G5) R4014.1 R4015.1
GPIO5_F: R4015.2 U4001.3(WP#(DQ2))
GPIO5_R: J2103.5 R4014.2
GPIO6: J2102.28(G6) R4016.1 R4017.1
GPIO6_F: R4017.2 U4001.5(DI(DQ0))
GPIO6_R: J2103.8 R4016.2
GPIO7: J2102.26(G7) R4018.1 R4019.1
GPIO7_F: R4019.2 U4001.6(CLK)
GPIO7_R: J2103.7 R4018.2
GPIO8: J2102.27(G8) R4020.1 R4021.1
GPIO8_F: R4021.2 U4001.2(DO(DQ1))
GPIO8_MFI: J2104.3(+) J2109.1 R2102.2 U2101.6(SCL)
GPIO8_R: J2104.2(+) R4020.2
GPIO8_RR: J2103.10 J2104.1(+)
GPIO9: J2102.24(G9) R4022.1 R4023.1
GPIO9_F: R4023.2 U4001.7(NC(DQ3))
GPIO9_MFI: J2105.3(+) J2110.1 R2101.2 U2101.2(SDA)
GPIO9_R: J2105.2(+) R4022.2
GPIO9_RR: J2103.9 J2105.1(+)
GPIO10: J2102.23(G10) R4024.1 R4025.1
GPIO10_F: R4025.2 U4001.1(CS#)
GPIO10_R: J2103.12 R4024.2
GPIO11: J2101.10 J2102.12(G11) J2206.2(+) R4103.2
GPIO11_STRAP_H: J2206.1(+) R2113.1
GPIO11_STRAP_L: J2206.3(+) R2114.1
GPIO12: J2102.11(G12) J2201.2(+) R4002.1 R4003.1
GPIO12_R: J2101.9 R4002.2 R4101.2
GPIO12_STRAP_H: J2201.1(+) R2208.1
GPIO12_STRAP_L: J2201.3(+) R2204.1
GPIO13: J2102.10(G13) J2205.2(+) R4004.1 R4005.1
GPIO13_R: J2101.8 R4004.2 R4102.2
GPIO13_STRAP_H: J2205.1(+) R2207.1
GPIO13_STRAP_L: J2205.3(+) R2205.1
GPIO14: J2102.9(G14) R4006.1 R4007.1
GPIO14_R: J2101.7 R4006.2 R4104.2
GPIO15: J2102.7(G15) J2203.2(+) R4008.1 R4009.1
GPIO15_R: J2101.6 R4008.2 R4105.2
GPIO15_SRTAP_H: J2203.1(+) R2209.1
GPIO15_SRTAP_L: J2203.3(+) R2202.1
GPIO16: J2102.6(G16) J2202.2(+) R4010.1 R4011.1
GPIO16_R: J2101.5 R4010.2
GPIO16_SRTAP_H: J2202.1(+) R2210.1
GPIO16_SRTAP_L: J2202.3(+) R2203.1
GPIO17: J2102.4(G17) R4012.1 R4013.1
GPIO17_R: J2101.4 R4012.2
GPIO18: J2101.3 J2102.3(G18)
GPIO19: J2101.2 J2102.2(G19) J3003.2
GPIO20: J2101.1 J2102.1(G20) J3002.2
JTAG_M_VCC: C9001.1 J9001.1(+) J9001.2(+) R9001.1
LED5: D2001.2(CATHODE) R2003.1
LED_5V: D2002.2(CATHODE) R2004.1
MK20_RST: C3002.1 J3005.1 Q3001.3(DRAIN)
RESETB_TGT3V3: Q3002.1(G) R3002.2 R3014.2 SW3001.1
RTC_EINT: J2101.12 J2102.14(RTC_EINT) R2020.2 S2006.1
SDA_JTAG_TCLK: J3004.9(+) U3002.12(JTAG_TCLK/SWD_CLK/EZP_CLK/TSI0_CH1/PTA0/UART0_CTS/UART0_COL/FTM0_CH5)
SDA_JTAG_TDI: J3004.5(+) U3002.13(JTAG_TDI/EZP_DI/TSI0_CH2/PTA1/UART0_RX/FTM0_CH6)
SDA_JTAG_TDO: J3004.13(+) U3002.14(JTAG_TDO/TRACE_SWO/EZP_DO/TSI0_CH3/PTA2/UART0_TX/FTM0_CH7)
SDA_JTAG_TMS: J3004.7(+) R3017.2 U3002.15(JTAG_TMS/SWD_DIO/TSI0_CH4/PTA3/UART0_RTS/FTM0_CH0)
SDA_JTAG_TRST: J3004.3(+) R3006.2 TP3011.1(TP) U3002.19(RESET#)
SDA_SPI0_CS: TP3009.1(TP) U3002.23(ADC0_SE4B/CMP1_IN0/TSI0_CH15/PTC2/SPI0_PCS2/UART1_CTS#/FTM0_CH1/I2S0_TX_FS) U3003.4(CS_B)
SDA_SPI0_RST_B: TP3008.1(TP) U3002.22(ADC0_SE15/TSI0_CH14/PTC1/SPI0_PCS3/UART1_RTS#/FTM0_CH0/I2S0_TXD0) U3003.3(RST_B)
SDA_SPI0_SCK: TP3007.1(TP) U3001.12(4A) U3002.26(PTC5/SPI0_SCK/LPTMR0_ALT2/I2S0_RXD0/CMP0_OUT) U3003.2(SCK)
SDA_SPI0_SIN: TP3006.1(TP) U3001.8(3Y) U3002.28(CMP0_IN1/PTC7/SPI0_SIN/USB_SOF_OUT/I2S0_RX_FS) U3003.8(SO)
SDA_SPI0_SOUT: TP3010.1(TP) U3001.2(1A) U3002.27(CMP0_IN0/PTC6/SPI0_SOUT/PDB0_EXTRG/I2S0_RX_BCLK/I2S0_MCLK) U3003.1(SI)
SDA_SWD_EN: J3001.3 R3008.2 U3001.10(3OE#) U3001.13(4OE#) U3002.16(NMI/EZP_CS/TSI0_CH5/PTA4/FTM0_CH1)
SDA_SWD_OE_B: R3007.2 U3001.1(1OE#) U3002.20(ADC0_SE8/TSI0_CH0/PTB0/I2C0_SCL/FTM1_CH0/FTM1_QD_PHA)
SPIMST_B_CS: R4013.2 U4002.1(/CS)
SPIMST_B_SCK: R4011.2 U4002.6(CLK)
SPIMST_B_SIO0: R4009.2 U4002.5(DI(IQ0))
SPIMST_B_SIO1: R4007.2 U4002.2(DO(IQ1))
SPIMST_B_SIO2: R4005.2 U4002.3(/WP(IQ2))
SPIMST_B_SIO3: R4003.2 U4002.7(/HOLD(IQ3))
SYS_RST_N_M: R2002.2 S2001.1
USB_DM: CON3001.2(D-) ESD3002.1(D2) R3004.1
USB_DP: CON3001.3(D+) ESD3002.2(D1) R3005.1
V_2AA: J2001.1 Q2001.3(D) R2006.1
V_2AA_B_I: C2006.1 J2003.3(+) Q2001.2(S) R2006.2 R2017.1 U2002.5(VIN) U2002.8(VINA)
V_2AA_MM: Q2001.1(G) R2005.1
V_2AA_O_3V3: C2011.1 J2002.3(+) R2015.1 U2002.1(VOUT)
V_B_1: L2002.2 U2002.4(LX1)
V_B_2: L2002.1 U2002.2(LX2)
V_B_FB: R2015.2 R2016.1 U2002.10(FB)
V_B_PS: R2017.2 R2018.2 U2002.7(PS)
VRTC: J2007.2 J2102.16(VRTC) R2008.2 R2019.1 S2006.2
VRTC_IN: J2003.2(+) J2007.1 R2008.1
VRTC_MM: J2008.1 R2019.2
VSW2: L2001.1 U2001.3(LX/SW)
N19137057: C2101.1 J2106.2 R2101.1 R2102.1 R2104.1 U2101.8(VCC)
N19176000: C3004.1 U3002.17(EXTAL/PTA18/FTM0_FLT2/FTM_CLKIN0) X3001.1(HOT)
N19176004: C3005.1 U3002.18(XTAL/PTA19/FTM1_FLT0/FTM_CLKIN1/LPTMR0_ALT1) X3001.3(HOT)
N19176010: R3011.2 R3012.1 U3002.32(PTD7/CMT_IRO/UART0_TX/FTM0_CH7/FTM0_FLT1)
N19176024: LED3001.2 U3002.29(PTD4/SPI0_PCS1/UART0_RTS#/FTM0_CH4/EWM_IN)
N19176065: TP3003.1(TP) U3002.11(VBAT)
N19176071: TP3001.1(TP) U3002.10(EXTAL32)
N19176073: TP3002.1(TP) U3002.9(XTAL)
N19176075: C3006.1 U3002.5(VOUT33)
N19176081: R3004.2 U3002.4(USB0_DM)
N19176083: R3005.2 U3002.3(USB0_DP)
N19176140: R3014.1 R3015.1 TP3012.1(TP) U3002.21(ADC0_SE9/TSI0_CH6/PTB1/I2C0_SDA/FTM1_CH1/FTM1_QD_PHB)
N19176148: J3003.1 U3002.25(PTC4/SPI0_PCS0/UART1_TX/FTM0_CH3/CMP1_OUT)
N19176150: J3002.1 U3002.24(CMP1_IN1/PTC3/SPI0_PCS1/UART1_RX/FTM0_CH2/CLKOUT/I2S0_TX_BCLK)
N19183861: LED3001.1 R3013.1
N19224016: TP3004.1(TP) U3001.5(2A)
N19224018: TP3005.1(TP) U3001.6(2Y)
N19224201: R3009.1 U3001.11(4Y)
N19224206: R3010.1 U3001.9(3A)
N19224211: J3001.2 U3001.4(2OE#)
N19236641: J2014.2 R2013.1
N19237278: Q3001.1(G) Q3002.3(DRAIN) R3003.2
N19256127: R3016.2 U3001.3(1Y)
N19269176: C4002.1 C4003.1 J4001.2 U4002.8(VCC)

Not connected (* = marked no-connect by the designer): CON3001 4(ID)*; J2101 11*; J3004 11(+)* 15(+)* 17(+)* 19(+)*; J9001 11(+)* 15(+)* 17(+)* 19(+)*; M1 1*; M2 1*; M3 1*; M4 1*; SW3001 2* 4*; U2101 3(NC)* 4(NC)* 5(NC)*; U3002 30(ADC0_SE6B/PTD5/SPI0_PCS2/UART0_CTS#/UART0_COL#/FTM0_CH5/EWM_OUT#)* 31(ADC0_SE7b/PTD6/SPI0_PCS3/UART0_RX/FTM0_CH6/FTM0_FLT0)*

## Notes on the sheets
sheet 1
- Host Interface Enable
- {GPIO4}
  0:Disable Host Interface at boot(default)
  1:Enable Host Interface
- Host Interface Select(active if HIF_EN=1)
- {GPIO13}
  1: host interface via SDIO slave (default)
  0: host interface via SPI slave
- SLT_MODE
- {GPIO11}
  0: normal (default,internal pull)
  1: SLT
- DL_MODE_B
- {GPIO12}
  1: no download (default,internal pull)
  0: UART download
- JTAG_FIX_B
- {GPIO15}
  1: JTAG pins as gpio (default,internal pull)
  0: JTAG pins fixed for JTAG use
- BROM_BYPASS_B
- {GPIO16}
  1: run with bootrom (default,internal pull)
  0: bypass bootrom
sheet 2
- JTAG
- JTRST
- JTDI
- JTMS
- JTCK
- JTDO
sheet 3
- Co-pad
- Note: 40-1
- GPIO5: SFSWP
  GPIO6: SFSOUT
  GPIO7: SFSCK
  GPIO8: SFSIN
  GPIO9: SFSHOLD
  GPIO10: SFSCS0
- SHOLD : SIO3
  SWP : SIO2
  SOUT : SQI_SI : DQ0
  SIN : SQI_SO : DQ1
- MXIC MX25U12835FZNI-10G,
  1.8V,128Mb,WSON 6*5:
- Co-pad
- SPI Flash/ SO8
sheet 4
- USER LED
sheet 5
- To UART TX
- Connect to MCU
- To UART RX
- UART
- Buffer for SWD input/output
- MK20 JTAG connector
- JTMS
- JTCK
- JTMS
- For RESETB LVS
- SPI FLASH MEMORY
sheet 6
- IC Power Consumption Measurement
- 5V
- 3V3
- DC_DC_3V3
- RTC Domain Power Measurement
- 2xAA Battery
- EINT(GPIO)
- AA
- Reverse
  voltage
  protection
- Reset Botton
sheet 7
- MT7686_MT7682
  Module
- USB1
- SCL0
- SDA0
- GND
- GND
- GND
- GND
